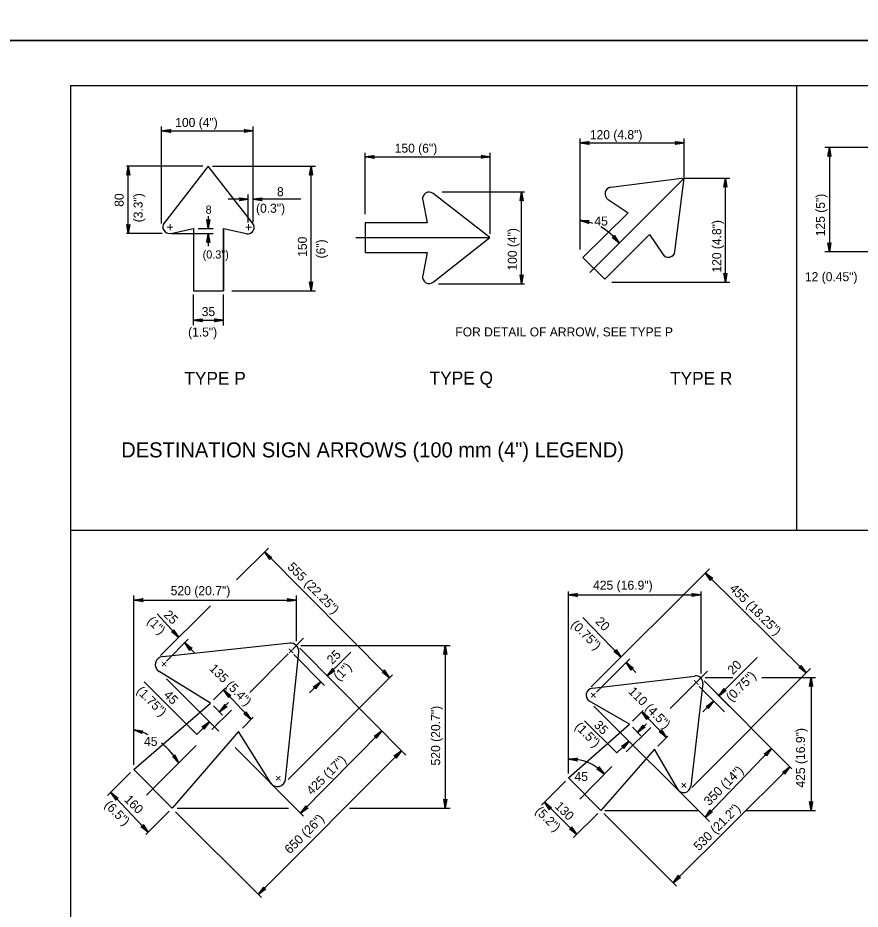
# Model space of a CAD drawing. Extents: x 637580 to 641849, y 297270 to 299646.
# Drawn here: x 640966.8 to 641247.2, y 298762.6 to 299059.1 of the extents above; entities that cross this region are included whole.
import ezdxf

# ---------------------------------------------------------------- set-up
doc = ezdxf.new("R2010")
doc.units = 0
for name, color, linetype in [('1', 7, 'Continuous'), ('2', 7, 'Continuous'), ('3', 7, 'Continuous'), ('XCS-GRID-HVGL', 7, 'Continuous')]:
    doc.layers.add(name, color=color, linetype=linetype)

# ---------------------------------------------------------------- blocks, each defined once
blk = doc.blocks.new('RARROW')
at = {"layer": '3'}
blk.add_lwpolyline([(-2.2695, 0.285), (-2.184875, 0.12075), (0, 0), (-2.2695, 0.285), (-2.38575, 0.384625), (0, 0), (-2.183125, -0.108), (-2.262875, -0.2705), (0, 0), (-2.38575, -0.379125), (-2.262875, -0.2705)], dxfattribs=at)

msp = doc.modelspace()

# ---------------------------------------------------------------- linework, layer by layer
at = {"layer": '1'}
for q in [(641770.31, 299036.63), (640984.31, 298472.63)]:
    msp.add_line((640984.31, 299036.63), q, dxfattribs=at)
for points in [[(641226.06, 298888.5), (641226.06, 299036.63)], [(641770.31, 298888.5), (640984.31, 298888.5)]]:
    msp.add_lwpolyline(points, dxfattribs=at)
at = {"layer": '2'}
for p, q in [((641014.69, 298990.75), (641014.69, 299023)), ((641014.69, 299021.5), (641045.19, 299021.5)), ((641045.19, 298991.13), (641045.19, 299023)), ((641153.94, 298982), (641153.94, 299019)), ((641188.56, 299006.13), (641188.56, 299019)), ((641153.94, 299017.5), (641188.56, 299017.5)), ((641267.56, 299016), (641235.44, 299016)), ((641236.94, 299016), (641236.94, 298981.25)), ((641082.44, 298993.75), (641082.44, 299014.25)), ((641082.44, 299012.88), (641124.06, 299012.88)), ((641124.06, 298987.25), (641124.06, 299014.25)), ((641028.44, 299009.75), (641002.94, 299009.75)), ((641003.56, 298987.38), (641003.56, 299009.75)), ((641030.19, 299009.75), (641015.44, 298990.75)), ((641045.06, 298990.75), (641030.19, 299009.75)), ((641031.56, 299009.75), (641065.94, 299009.75)), ((641064.44, 298968.25), (641064.44, 299009.75)), ((641157.19, 298974.38), (641188.56, 299005.75)), ((641188.56, 299005.75), (641164.19, 299002.63)), ((641185.44, 298981.38), (641188.56, 299005.75)), ((641188.81, 299005.75), (641203.81, 299005.75)), ((641202.31, 298971.13), (641202.31, 299005.75)), ((641043.44, 298991), (641043.44, 299000.38)), ((641045.19, 298991.13), (641045.19, 299000.38)), ((641123.94, 298986), (641105.06, 299000.63)), ((641108.06, 299001.25), (641135.44, 299001.25)), ((641134.46, 298970.63), (641134.46, 299001.25)), ((641043.44, 298998.75), (641036.81, 298998.75)), ((641061.01, 298998.75), (641045.19, 298998.75)), ((641101.56, 298998.5), (641103.06, 298990.88)), ((641163.31, 298998.63), (641169.94, 298994.25)), ((641169.94, 298994.25), (641154.81, 298979.38)), ((641030.19, 298993.13), (641030.19, 298989)), ((641017.69, 298987.38), (641025.31, 298989)), ((641025.31, 298989), (641025.31, 298968.25)), ((641025.31, 298989), (641025.31, 298968.25)), ((641026.81, 298989), (641031.81, 298989)), ((641035.31, 298968.25), (641035.31, 298989)), ((641035.31, 298989), (641042.94, 298987.38)), ((641035.31, 298989), (641035.31, 298968.25)), ((641035.31, 298989), (641035.31, 298968.25)), ((641082.44, 298990.88), (641082.44, 298981)), ((641103.06, 298990.88), (641082.44, 298990.88)), ((641014.81, 298987.38), (641002.94, 298987.38)), ((641017.94, 298987.38), (641031.81, 298987.38)), ((641030.19, 298987.38), (641030.19, 298983.13)), ((641079.31, 298986), (641123.94, 298986)), ((641105.06, 298971.13), (641123.94, 298986)), ((641162.19, 298972.13), (641177.06, 298987)), ((641177.06, 298987), (641181.44, 298980.5)), ((641082.44, 298981), (641103.06, 298981)), ((641103.06, 298981), (641101.56, 298973.38)), ((641154.81, 298979.38), (641162.19, 298972.13)), ((641251.81, 298981.25), (641235.44, 298981.25)), ((641106.81, 298970.63), (641135.44, 298970.63)), ((641164.56, 298971.13), (641203.81, 298971.13)), ((641025.31, 298968.25), (641035.31, 298968.25)), ((641038.06, 298968.25), (641065.94, 298968.25)), ((641025.31, 298956.88), (641025.31, 298967.13)), ((641035.31, 298956.75), (641035.31, 298967.13)), ((641025.31, 298958.5), (641035.31, 298958.5)), ((641039.62, 298872.11), (641050.28, 298882.68)), ((641048.98, 298881.39), (641090.44, 298839.63)), ((641157.69, 298836.5), (641197.03, 298875.84)), ((641195.61, 298874.43), (641229.19, 298841.17)), ((641005.44, 298810.63), (641005.44, 298866.88)), ((641059.56, 298851.75), (641059.56, 298866.88)), ((641150.06, 298807.75), (641150.06, 298868.25)), ((641150.06, 298867.13), (641150.06, 298867.13)), ((641150.06, 298867.13), (641194.19, 298867.13)), ((641194.19, 298841), (641194.19, 298868.25)), ((641005.44, 298865.38), (641059.56, 298865.38)), ((641014.31, 298847), (641030.98, 298863.54)), ((641020.36, 298853), (641013.18, 298860.81)), ((641167.63, 298846.44), (641154.9, 298859.59)), ((641016.31, 298845.13), (641023.56, 298852.38)), ((641061.94, 298852.75), (641058.41, 298849.2)), ((641015.06, 298846.63), (641057.44, 298851.13)), ((641022.4, 298851.21), (641025.69, 298847.75)), ((641059.56, 298850.25), (641059.56, 298850.25)), ((641059.56, 298850.25), (641059.56, 298850.25)), ((641059.56, 298850.25), (641059.56, 298850.25)), ((641060.69, 298849.38), (641095.95, 298813.81)), ((641061.06, 298850.25), (641110.69, 298850.25)), ((641109.06, 298850.25), (641109.06, 298796.13)), ((641056.75, 298847.53), (641043.98, 298834.69)), ((641060.19, 298848.13), (641055.81, 298805.75)), ((641058.69, 298847.25), (641068.94, 298837)), ((641069.77, 298840.21), (641077.68, 298848.12)), ((641159.44, 298834.75), (641170.56, 298845.88)), ((641200.15, 298833.52), (641212.91, 298846.28)), ((641015.31, 298843.88), (641015.31, 298843.88)), ((641169.31, 298844.63), (641172.54, 298841.27)), ((641030.94, 298831.13), (641013.81, 298841.63)), ((641056.81, 298805.75), (641091.56, 298840.5)), ((641158.06, 298836.13), (641192.19, 298840.13)), ((641183.98, 298829.29), (641196.31, 298841.75)), ((641191.19, 298803), (641230.6, 298842.59)), ((641008.9, 298838.18), (641026.36, 298820.67)), ((641016.31, 298839.25), (641033.68, 298821.84)), ((641067.69, 298838.25), (641063.94, 298834.5)), ((641194.81, 298837.63), (641190.81, 298803.5)), ((641194.19, 298839.63), (641194.19, 298839.63)), ((641194.19, 298839.63), (641194.19, 298839.63)), ((641195.19, 298838.5), (641203.69, 298830)), ((641195.19, 298838.5), (641224.46, 298809.23)), ((641195.56, 298839.63), (641204.84, 298839.63)), ((641214.47, 298839.63), (641232.31, 298839.63)), ((641230.81, 298839.63), (641230.81, 298839.63)), ((641230.81, 298839.63), (641230.81, 298795.38)), ((641031.94, 298832.25), (641035.92, 298836.23)), ((641035.31, 298835.5), (641044.43, 298825.71)), ((641193.56, 298836.63), (641202.06, 298828.25)), ((641005.44, 298809), (641030.94, 298831.13)), ((641030.94, 298831.13), (641030.94, 298831.13)), ((641033.94, 298828.25), (641036.94, 298831.38)), ((641170.44, 298824.13), (641157.06, 298831.75)), ((641198.37, 298831.77), (641194.78, 298828.19)), ((641031.43, 298822.33), (641037.94, 298828.75)), ((641031.94, 298830.25), (641034.94, 298827.13)), ((641158.56, 298830.13), (641197, 298791.69)), ((641171.44, 298825.13), (641174.98, 298828.66)), ((641174.52, 298828.21), (641182.69, 298819.69)), ((641030.56, 298824.88), (641026.36, 298820.67)), ((641041.56, 298822.75), (641045.14, 298826.43)), ((641155.37, 298825.18), (641166.18, 298814.53)), ((641150.06, 298806.25), (641170.44, 298824.13)), ((641169.31, 298814.88), (641177.5, 298822.96)), ((641171.44, 298823.13), (641174.19, 298820.25)), ((641173.09, 298821.4), (641176.06, 298824.25)), ((641005.44, 298821.88), (641005.44, 298821.88)), ((641040.31, 298821.63), (641018.19, 298796.13)), ((641040.31, 298821.63), (641040.31, 298821.63)), ((641050.94, 298804.75), (641040.31, 298821.63)), ((641087.97, 298821.85), (641060.94, 298794.5)), ((641174.69, 298820), (641174.69, 298820)), ((641179.81, 298816.75), (641183.16, 298820.17)), ((641009.69, 298800.5), (641026.18, 298817)), ((641015.19, 298817.38), (641015.19, 298817.38)), ((641039.1, 298816.4), (641061.94, 298793.5)), ((641170.25, 298818.44), (641166.18, 298814.53)), ((641171.69, 298817.13), (641171.69, 298817.13)), ((641195.59, 298793.1), (641217.62, 298816.07)), ((641217.56, 298816), (641217.56, 298816)), ((641046.81, 298767.5), (641094.54, 298815.23)), ((641178.69, 298815.75), (641160.81, 298795.38)), ((641186.44, 298802.5), (641178.69, 298815.75)), ((641004.31, 298808), (640996.69, 298800.38)), ((641018.19, 298796.13), (641005.44, 298809)), ((641153.81, 298799.13), (641164.56, 298810)), ((641184.94, 298771.38), (641223.78, 298809.91)), ((641149.06, 298805.13), (641141.06, 298797.13)), ((641160.81, 298795.38), (641150.06, 298806.25)), ((640997.81, 298801.38), (641010.22, 298788.16)), ((641155.56, 298800.88), (641155.56, 298800.88)), ((641188.31, 298800.38), (641188.31, 298800.38)), ((641019.81, 298796.13), (641056.95, 298796.13)), ((641077.16, 298796.13), (641110.69, 298796.13)), ((641142.06, 298798.13), (641152.81, 298787.38)), ((641162.19, 298795.38), (641193.31, 298795.38)), ((641209.08, 298795.38), (641232.31, 298795.38)), ((641017.19, 298795.13), (641009.44, 298787.38)), ((641019.31, 298795), (641047.94, 298766.5)), ((641159.81, 298794.38), (641151.81, 298786.38)), ((641161.81, 298794.38), (641186.06, 298770.25))]:
    msp.add_line(p, q, dxfattribs=at)
for centre, radius, start, end in [((641103.67, 298998.98), 2.16, 51.9885, 191.4212), ((641164.46, 299000.56), 2.21, 96.9885, 236.4212), ((641151.82, 298973.2), 18.65, 70.1319, 83.4312), ((641017.23, 298989.56), 2.16, 141.9885, 281.4212), ((641043.36, 298989.42), 2.16, 258.5788, 38.0115), ((641151.82, 298973.2), 18.65, 35.9325, 61.1367), ((641183.34, 298981.69), 2.21, 213.5788, 353.0115), ((641103.67, 298972.87), 2.16, 168.5788, 308.0115), ((641057.62, 298848.39), 2.7, 354.0498, 95.9502), ((641015.27, 298843.98), 2.7, 95.9502, 238.4461), ((641192.45, 298837.83), 2.36, 353.2204, 96.7795), ((641158.32, 298833.78), 2.36, 96.7795, 240.0676), ((640999.93, 298799.29), 23.64, 64.1532, 76.5153), ((640999.93, 298799.29), 23.64, 30.0986, 51.4068), ((641150.92, 298797.35), 15.12, 42.2634, 93.2507), ((641150.92, 298797.35), 15.12, 42.2634, 43.751), ((641053.21, 298806.04), 2.7, 211.5539, 354.0498), ((641188.39, 298803.71), 2.36, 209.9324, 353.2204)]:
    msp.add_arc(centre, radius, start, end, dxfattribs=at)
at = {"layer": 'XCS-GRID-HVGL'}
for points in [[(640944.31, 299645.63), (641785.31, 299645.63), (641785.31, 299051.63), (640944.31, 299051.63)], [(640944.31, 299051.63), (641785.31, 299051.63), (641785.31, 298457.63), (640944.31, 298457.63)]]:
    msp.add_lwpolyline(points, close=True, dxfattribs=at)

# ---------------------------------------------------------------- block references
at = {"layer": '2'}
for p, xscale, yscale, rotation in [((641014.69, 299021.5), 1.2574347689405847, 1.3092961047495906, 180), ((641153.94, 299017.5), 1.2574347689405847, 1.3092961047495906, 180), ((641236.94, 299016), 1.2574347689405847, 1.3092961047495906, 89.99999999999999), ((641082.44, 299012.88), 1.2574347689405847, 1.3092961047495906, 180), ((641003.56, 299009.75), 1.2574347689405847, 1.3092961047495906, 89.99999999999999), ((641064.44, 299009.75), 1.2574347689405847, 1.3092961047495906, 89.99999999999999), ((641202.31, 299005.75), 1.2574347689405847, 1.3092961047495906, 89.99999999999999), ((641134.46, 299001.25), 1.2574347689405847, 1.3092961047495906, 89.99999999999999), ((641045.19, 298998.75), 1.2574347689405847, 1.3092961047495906, 180), ((641030.19, 298989), 1.2574347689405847, 1.3092961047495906, -90.00000000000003), ((641153.95, 298991.73), 1.2574347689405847, 1.3092961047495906, 169.44923148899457), ((641003.56, 298987.38), 1.2574347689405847, 1.3092961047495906, -90.00000000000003), ((641030.19, 298987.38), 1.2574347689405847, 1.3092961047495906, 89.99999999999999), ((641166.92, 298984.14), 1.257434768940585, 1.3092961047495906, -49.33525857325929), ((641236.94, 298981.25), 1.2574347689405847, 1.3092961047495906, -90.00000000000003), ((641134.46, 298970.63), 1.2574347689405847, 1.3092961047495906, -90.00000000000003), ((641202.31, 298971.13), 1.2574347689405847, 1.3092961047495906, -90.00000000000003), ((641064.44, 298968.25), 1.2574347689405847, 1.3092961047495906, -90.00000000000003), ((641025.31, 298958.5), 1.2574347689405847, 1.3092961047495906, 180), ((641048.98, 298881.39), 1.257434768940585, 1.3092961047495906, 133.27939444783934), ((641195.61, 298874.43), 1.2574347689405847, 1.3092961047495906, 135.61891032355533), ((641150.06, 298867.13), 1.2574347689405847, 1.3092961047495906, 180), ((641005.44, 298865.38), 1.2574347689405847, 1.3092961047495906, 180), ((641020.36, 298853), 1.257434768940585, 1.3092961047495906, -46.72060555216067), ((641022.4, 298851.21), 1.257434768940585, 1.3092961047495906, 133.27939444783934), ((641109.06, 298850.25), 1.2574347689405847, 1.3092961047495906, 89.99999999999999), ((641167.63, 298846.44), 1.257434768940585, 1.3092961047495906, -46.72060555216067), ((641169.31, 298844.63), 1.257434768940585, 1.3092961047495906, 133.27939444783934), ((641229.19, 298841.17), 1.257434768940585, 1.3092961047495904, -44.89188331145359), ((641069.77, 298840.21), 1.2574347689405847, 1.3092961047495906, -136.72060555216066), ((641090.44, 298839.63), 1.257434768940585, 1.3092961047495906, -46.72060555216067), ((641067.69, 298838.25), 1.257434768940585, 1.3092961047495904, 43.27939444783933), ((641230.81, 298839.63), 1.2574347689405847, 1.3092961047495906, 89.99999999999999), ((641035.31, 298835.5), 1.257434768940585, 1.3092961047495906, 133.27939444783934), ((641200.15, 298833.52), 1.257434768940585, 1.3092961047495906, -134.67395762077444), ((641198.37, 298831.77), 1.257434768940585, 1.309296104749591, 45.50955017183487), ((641033.94, 298828.25), 1.2574347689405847, 1.3092961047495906, -136.72060555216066), ((641044.43, 298825.71), 1.257434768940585, 1.3092961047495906, -46.72060555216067), ((641174.52, 298828.21), 1.257434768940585, 1.3092961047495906, 133.27939444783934), ((641030.56, 298824.88), 1.257434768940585, 1.3092961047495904, 43.27939444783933), ((641005.44, 298822.28), 1.2574347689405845, 1.3092961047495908, 163.80944818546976), ((641087.97, 298821.85), 1.257434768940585, 1.3092961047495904, 43.27939444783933), ((641173.09, 298821.4), 1.2574347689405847, 1.3092961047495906, -136.72060555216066), ((641182.69, 298819.69), 1.257434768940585, 1.3092961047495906, -46.72060555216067), ((641170.25, 298818.44), 1.257434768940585, 1.3092961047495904, 43.27939444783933), ((641217.62, 298816.07), 1.2574347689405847, 1.3092961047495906, 47.006569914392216), ((641020.37, 298811.15), 1.257434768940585, 1.3092961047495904, -55.73238514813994), ((641094.54, 298815.23), 1.257434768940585, 1.3092961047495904, 43.27939444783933), ((641150.06, 298812.45), 1.2574347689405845, 1.3092961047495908, 178.3226404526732), ((641223.78, 298809.91), 1.2574347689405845, 1.3092961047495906, 44.994727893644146), ((641162.11, 298807.52), 1.2574347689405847, 1.3092961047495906, -42.27401175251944), ((640997.81, 298801.38), 1.257434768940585, 1.3092961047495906, 133.27939444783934), ((641109.06, 298796.13), 1.2574347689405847, 1.3092961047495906, -90.00000000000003), ((641142.06, 298798.13), 1.257434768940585, 1.3092961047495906, 133.27939444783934), ((641230.81, 298795.38), 1.2574347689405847, 1.3092961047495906, -90.00000000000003), ((641060.94, 298794.5), 1.2574347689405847, 1.3092961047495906, -136.72060555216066), ((641195.59, 298793.1), 1.2574347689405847, 1.3092961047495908, -132.89815458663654), ((641010.22, 298788.16), 1.257434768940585, 1.3092961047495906, -46.72060555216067), ((641152.81, 298787.38), 1.257434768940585, 1.3092961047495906, -46.72060555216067), ((641184.94, 298771.38), 1.257434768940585, 1.3092961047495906, -134.7356981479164), ((641046.81, 298767.5), 1.2574347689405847, 1.3092961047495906, -136.72060555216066)]:
    msp.add_blockref('RARROW', p, dxfattribs=dict(at, xscale=xscale, yscale=yscale, rotation=rotation))
at = {"layer": '2', "xscale": 1.2574347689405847, "yscale": 1.3092961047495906}
for p in [(641045.19, 299021.5), (641188.56, 299017.5), (641124.06, 299012.88), (641043.44, 298998.75), (641035.31, 298958.5), (641194.19, 298867.13), (641059.56, 298865.38)]:
    msp.add_blockref('RARROW', p, dxfattribs=at)

# ---------------------------------------------------------------- texts
at = {"layer": '2'}
for s, height, p in [('100 (4")', 3, (641019.21, 299022.82)), ('120 (4.8")', 3, (641157.2, 299018.75)), ('150 (6")', 3, (641092.26, 299014.25)), ('8', 3, (641053.08, 298999.77)), ('(0.3")', 3, (641046.1, 298994.27)), ('8', 2.7, (641029.31, 298993.95)), ('45', 3.022, (641158.69, 298990)), ('+', 3.02, (641016.31, 298988)), ('+', 3.02, (641042.44, 298988)), ('(0.3")', 2.699, (641028.33, 298979.05)), (' 12 (0.45")', 3, (641227.68, 298971.5)), ('35', 3, (641028.02, 298959.89)), ('(1.5")', 3, (641023.48, 298953.09)), ('FOR DETAIL OF ARROW, SEE TYPE P', 3, (641112.44, 298953.13)), ('TYPE P', 4.3, (641022.24, 298937.03)), ('TYPE Q', 4.3, (641103.88, 298937.13)), ('TYPE R', 4.3, (641183.89, 298937.03)), ('DESTINATION SIGN ARROWS (100 mm (4") LEGEND)', 5, (641001.23, 298912.88)), ('520 (20.7")', 3.0217, (641017.69, 298867.03)), ('425 (16.9")', 3.0217, (641158.25, 298868.84)), ('45', 3.022, (641008.81, 298816.88)), ('45', 3.022, (641152.08, 298805.19))]:
    msp.add_text(s, height=height, dxfattribs=at).set_placement(p)
for s, height, rotation, p in [('80', 3, 90, (641002.04, 298996.26)), ('(3.3")', 3, 90, (641008.35, 298991.09)), ('125 (5")', 3, 90, (641235.42, 298986.46)), ('120 (4.8")', 3, 90, (641200.92, 298974.37)), ('100 (4")', 3, 90, (641132.89, 298975.03)), ('150', 3, 90, (641063.01, 298979.62)), ('(6")', 3, 90, (641069.16, 298979.08)), ('555 (22.25")', 3.0217, 315, (641056.34, 298876.17)), ('455 (18.25")', 3.0217, 315, (641203.45, 298869)), ('25 ', 3.022, 315, (641015.15, 298860.26)), ('(1")', 3.022, 315, (641009.65, 298858.17)), ('(0.75")', 3.022, 315, (641150.7, 298857.01)), (' 20', 3.022, 315, (641158.02, 298858.83)), ('+', 3.02, 45, (641057.96, 298846.6)), ('25', 3.022, 45, (641071.44, 298843.82)), ('+', 3.02, 45, (641015.69, 298842.25)), ('135 (5.4")', 3.022, 315, (641030.34, 298842.39)), ('(1")', 3.022, 45, (641073.68, 298838.3)), ('20', 3.022, 45, (641204.8, 298840.38)), ('(0.75")', 3.022, 45, (641204.29, 298831.44)), ('+', 3.02, 45, (641192.81, 298836.13)), ('(1.75")', 3.022, 315, (641006.06, 298834.96)), ('45 ', 3.022, 315, (641015.13, 298833.57)), ('+', 3.02, 45, (641158.56, 298831.88)), ('110 (4.5")', 3.022, 315, (641169.79, 298834.77)), ('520 (20.7")', 3.0217, 90, (641107.38, 298810.37)), ('35', 3.022, 315, (641158.35, 298823.56)), ('(1.5")', 3.022, 315, (641151.97, 298823.05)), ('425 (16.9")', 3.0217, 90, (641228.81, 298802.99)), ('425 (17")', 3.022, 45, (641064.69, 298800.34)), ('350 (14")', 3.022, 45, (641196.92, 298796.8)), ('+', 3.02, 45, (641053.69, 298804.25)), ('+', 3.02, 45, (641188.69, 298801.88)), ('(6.5")', 3.022, 315, (640995.41, 298796.98)), ('160', 3.022, 315, (641001.99, 298798.78)), ('(5.2")', 3.022, 315, (641138.79, 298794.97)), ('130', 3.022, 315, (641145.32, 298796.59)), ('530 (21.2")', 3.0217, 45, (641193.51, 298781.81)), ('650 (26")', 3.022, 45, (641057.38, 298780.74))]:
    msp.add_text(s, height=height, rotation=rotation, dxfattribs=at).set_placement(p)

doc.saveas('drawing.dxf')
